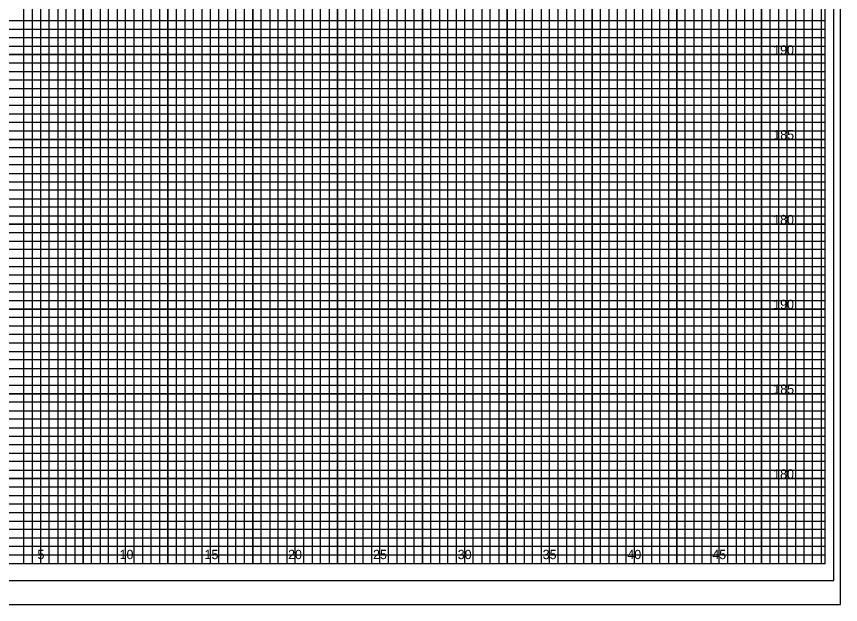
# Model space of a CAD drawing. Extents: x -4 to 103, y -2 to 67.
# Drawn here: x 54.82 to 103.4, y -2.43 to 32.25 of the extents above; entities that cross this region are included whole.
import ezdxf

# ---------------------------------------------------------------- set-up
doc = ezdxf.new("R2010")
doc.units = 0
for name, color, linetype in [('Old_Level_10', 7, 'Continuous'), ('Old_Level_16', 7, 'Continuous'), ('Old_Level_3', 7, 'Continuous'), ('Old_Level_4', 7, 'Continuous'), ('Old_Level_5', 7, 'Continuous'), ('Old_Level_6', 7, 'Continuous'), ('Old_Level_8', 7, 'Continuous'), ('Prop XS Dump Level', 7, 'Continuous'), ('Prop XSC Text', 7, 'Continuous')]:
    doc.layers.add(name, color=color, linetype=linetype)

msp = doc.modelspace()

# ---------------------------------------------------------------- linework, layer by layer
at = {"layer": 'Old_Level_10'}
for p, q in [((56.25, 0), (56.25, 65)), ((58.75, 0), (58.75, 65)), ((61.25, 0), (61.25, 65)), ((63.75, 0), (63.75, 65)), ((66.25, 0), (66.25, 65)), ((68.75, 0), (68.75, 65)), ((71.25, 0), (71.25, 65)), ((73.75, 0), (73.75, 65)), ((91.25, 0), (91.25, 63.425)), ((93.75, 0), (93.75, 63.425)), ((96.25, 0), (96.25, 63.425)), ((98.75, 0), (98.75, 63.425)), ((101.25, 0), (101.25, 63.425)), ((76.25, 0), (76.25, 62)), ((78.75, 0), (78.75, 62)), ((81.25, 0), (81.25, 62)), ((83.75, 0), (83.75, 62)), ((86.25, 0), (86.25, 62)), ((88.75, 0), (88.75, 62)), ((0, 30), (102.5, 30)), ((0, 27.5), (102.5, 27.5)), ((0, 25), (102.5, 25)), ((0, 22.5), (102.5, 22.5)), ((0, 20), (102.5, 20)), ((0, 17.5), (102.5, 17.5)), ((0, 15), (102.5, 15)), ((0, 12.5), (102.5, 12.5)), ((0, 10), (102.5, 10)), ((0, 7.5), (102.5, 7.5)), ((0, 5), (102.5, 5)), ((0, 2.5), (102.5, 2.5))]:
    msp.add_line(p, q, dxfattribs=at)
at = {"layer": 'Old_Level_3'}
msp.add_line((-3.5, -2.425), (103.4, -2.425), dxfattribs=at)
at = {"layer": 'Old_Level_4'}
msp.add_lwpolyline([(103, 66), (-2.8, 66), (-2.8, -1), (103, -1)], close=True, dxfattribs=at)
at = {"layer": 'Old_Level_5'}
msp.add_lwpolyline([(103.4, 67.4), (-3.5, 67.4), (-3.5, -2.425), (103.4, -2.425)], close=True, dxfattribs=at)
at = {"layer": 'Old_Level_6'}
msp.add_lwpolyline([(102.5, 65), (0, 65), (0, 0), (102.5, 0)], close=True, dxfattribs=at)
at = {"layer": 'Old_Level_8'}
for points in [[(56.25, 0), (56.25, 65)], [(58.75, 65), (58.75, 0), (61.25, 0), (61.25, 65)], [(63.75, 65), (63.75, 0), (66.25, 0), (66.25, 65)], [(68.75, 65), (68.75, 0), (71.25, 0), (71.25, 65)], [(73.75, 65), (73.75, 0), (76.25, 0), (76.25, 62)], [(88.75, 62), (88.75, 0), (91.25, 0), (91.25, 63.425)], [(93.75, 63.425), (93.75, 0), (96.25, 0), (96.25, 63.425)], [(98.75, 63.425), (98.75, 0), (101.25, 0), (101.25, 63.425)], [(78.75, 62), (78.75, 0), (81.25, 0), (81.25, 62)], [(83.75, 62), (83.75, 0), (86.25, 0), (86.25, 62)], [(0, 27.5), (102.5, 27.5), (102.5, 30), (0, 30)], [(0, 22.5), (102.5, 22.5), (102.5, 25), (0, 25)], [(0, 17.5), (102.5, 17.5), (102.5, 20), (0, 20)], [(0, 12.5), (102.5, 12.5), (102.5, 15), (0, 15)], [(0, 7.5), (102.5, 7.5), (102.5, 10), (0, 10)], [(0, 2.5), (102.5, 2.5), (102.5, 5), (0, 5)]]:
    msp.add_lwpolyline(points, dxfattribs=at)
at = {"layer": 'Prop XSC Text'}
for points in [[(54.75, 0), (55.25, 0), (55.25, 65)], [(55.75, 65), (55.75, 0), (56.75, 0), (56.75, 65)], [(57.25, 65), (57.25, 0), (57.75, 0), (57.75, 65)], [(58.25, 65), (58.25, 0), (59.25, 0), (59.25, 65)], [(59.75, 65), (59.75, 0), (60.25, 0), (60.25, 65)], [(60.75, 65), (60.75, 0), (61.75, 0), (61.75, 65)], [(62.25, 65), (62.25, 0), (62.75, 0), (62.75, 65)], [(63.25, 65), (63.25, 0), (64.25, 0), (64.25, 65)], [(64.75, 65), (64.75, 0), (65.25, 0), (65.25, 65)], [(65.75, 65), (65.75, 0), (66.75, 0), (66.75, 65)], [(67.25, 65), (67.25, 0), (67.75, 0), (67.75, 65)], [(68.25, 65), (68.25, 0), (69.25, 0), (69.25, 65)], [(69.75, 65), (69.75, 0), (70.25, 0), (70.25, 65)], [(70.75, 65), (70.75, 0), (71.75, 0), (71.75, 65)], [(72.25, 65), (72.25, 0), (72.75, 0), (72.75, 65)], [(73.25, 65), (73.25, 0), (74.25, 0), (74.25, 62)], [(89.75, 62), (89.75, 0), (90.25, 0), (90.25, 63.425)], [(90.75, 63.425), (90.75, 0), (91.75, 0), (91.75, 63.425)], [(92.25, 63.425), (92.25, 0), (92.75, 0), (92.75, 63.425)], [(93.25, 63.425), (93.25, 0), (94.25, 0), (94.25, 63.425)], [(94.75, 63.425), (94.75, 0), (95.25, 0), (95.25, 63.425)], [(95.75, 63.425), (95.75, 0), (96.75, 0), (96.75, 63.425)], [(97.25, 63.425), (97.25, 0), (97.75, 0), (97.75, 63.425)], [(98.25, 63.425), (98.25, 0), (99.25, 0), (99.25, 63.425)], [(99.75, 63.425), (99.75, 0), (100.25, 0), (100.25, 63.425)], [(100.25, 63.425), (100.75, 63.425), (100.75, 0), (101.75, 0), (101.75, 63.425), (102.25, 63.425), (102.25, 0)], [(74.75, 62), (74.75, 0), (75.25, 0), (75.25, 62)], [(75.75, 62), (75.75, 0), (76.75, 0), (76.75, 62)], [(77.25, 62), (77.25, 0), (77.75, 0), (77.75, 62)], [(78.25, 62), (78.25, 0), (79.25, 0), (79.25, 62)], [(79.75, 62), (79.75, 0), (80.25, 0), (80.25, 62)], [(80.75, 62), (80.75, 0), (81.75, 0), (81.75, 62)], [(82.25, 62), (82.25, 0), (82.75, 0), (82.75, 62)], [(83.25, 62), (83.25, 0), (84.25, 0), (84.25, 62)], [(84.75, 62), (84.75, 0), (85.25, 0), (85.25, 62)], [(85.75, 62), (85.75, 0), (86.75, 0), (86.75, 62)], [(87.25, 62), (87.25, 0), (87.75, 0), (87.75, 62)], [(88.25, 62), (88.25, 0), (89.25, 0), (89.25, 62)], [(0, 31.5), (102.5, 31.5), (102.5, 32), (0, 32)], [(0, 30.5), (102.5, 30.5), (102.5, 31), (0, 31)], [(0, 29), (102.5, 29), (102.5, 29.5), (0, 29.5)], [(0, 28), (102.5, 28), (102.5, 28.5), (0, 28.5)], [(0, 26.5), (102.5, 26.5), (102.5, 27), (0, 27)], [(0, 25.5), (102.5, 25.5), (102.5, 26), (0, 26)], [(0, 24), (102.5, 24), (102.5, 24.5), (0, 24.5)], [(0, 23), (102.5, 23), (102.5, 23.5), (0, 23.5)], [(0, 21.5), (102.5, 21.5), (102.5, 22), (0, 22)], [(0, 20.5), (102.5, 20.5), (102.5, 21), (0, 21)], [(0, 19), (102.5, 19), (102.5, 19.5), (0, 19.5)], [(0, 18), (102.5, 18), (102.5, 18.5), (0, 18.5)], [(0, 16.5), (102.5, 16.5), (102.5, 17), (0, 17)], [(0, 15.5), (102.5, 15.5), (102.5, 16), (0, 16)], [(0, 14), (102.5, 14), (102.5, 14.5), (0, 14.5)], [(0, 13), (102.5, 13), (102.5, 13.5), (0, 13.5)], [(0, 11.5), (102.5, 11.5), (102.5, 12), (0, 12)], [(0, 10.5), (102.5, 10.5), (102.5, 11), (0, 11)], [(0, 9), (102.5, 9), (102.5, 9.5), (0, 9.5)], [(0, 8), (102.5, 8), (102.5, 8.5), (0, 8.5)], [(0, 6.5), (102.5, 6.5), (102.5, 7), (0, 7)], [(0, 5.5), (102.5, 5.5), (102.5, 6), (0, 6)], [(0, 4), (102.5, 4), (102.5, 4.5), (0, 4.5)], [(0, 3), (102.5, 3), (102.5, 3.5), (0, 3.5)], [(0, 1.5), (102.5, 1.5), (102.5, 2), (0, 2)], [(0, 0.5), (102.5, 0.5), (102.5, 1), (0, 1)]]:
    msp.add_lwpolyline(points, dxfattribs=at)

# ---------------------------------------------------------------- texts
at = {"layer": 'Old_Level_16'}
for s, p in [('5', (56.057, 0.25)), ('10', (60.897, 0.25)), ('15', (65.906, 0.25)), ('20', (70.831, 0.25)), ('25', (75.84, 0.25)), ('30', (80.831, 0.25)), ('35', (85.84, 0.25)), ('40', (90.831, 0.25)), ('45', (95.84, 0.25))]:
    msp.add_text(s, height=0.55, dxfattribs=at).set_placement(p)
at = {"layer": 'Prop XS Dump Level'}
for s, p in [('190', (99.43, 30)), ('185', (99.438, 25)), ('180', (99.43, 20)), ('190', (99.43, 15)), ('185', (99.438, 10)), ('180', (99.43, 5))]:
    msp.add_text(s, height=0.55, dxfattribs=at).set_placement(p)

doc.saveas('drawing.dxf')
